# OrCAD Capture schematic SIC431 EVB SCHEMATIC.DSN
size Custom; title: SIC431 Demo Board; rev: D
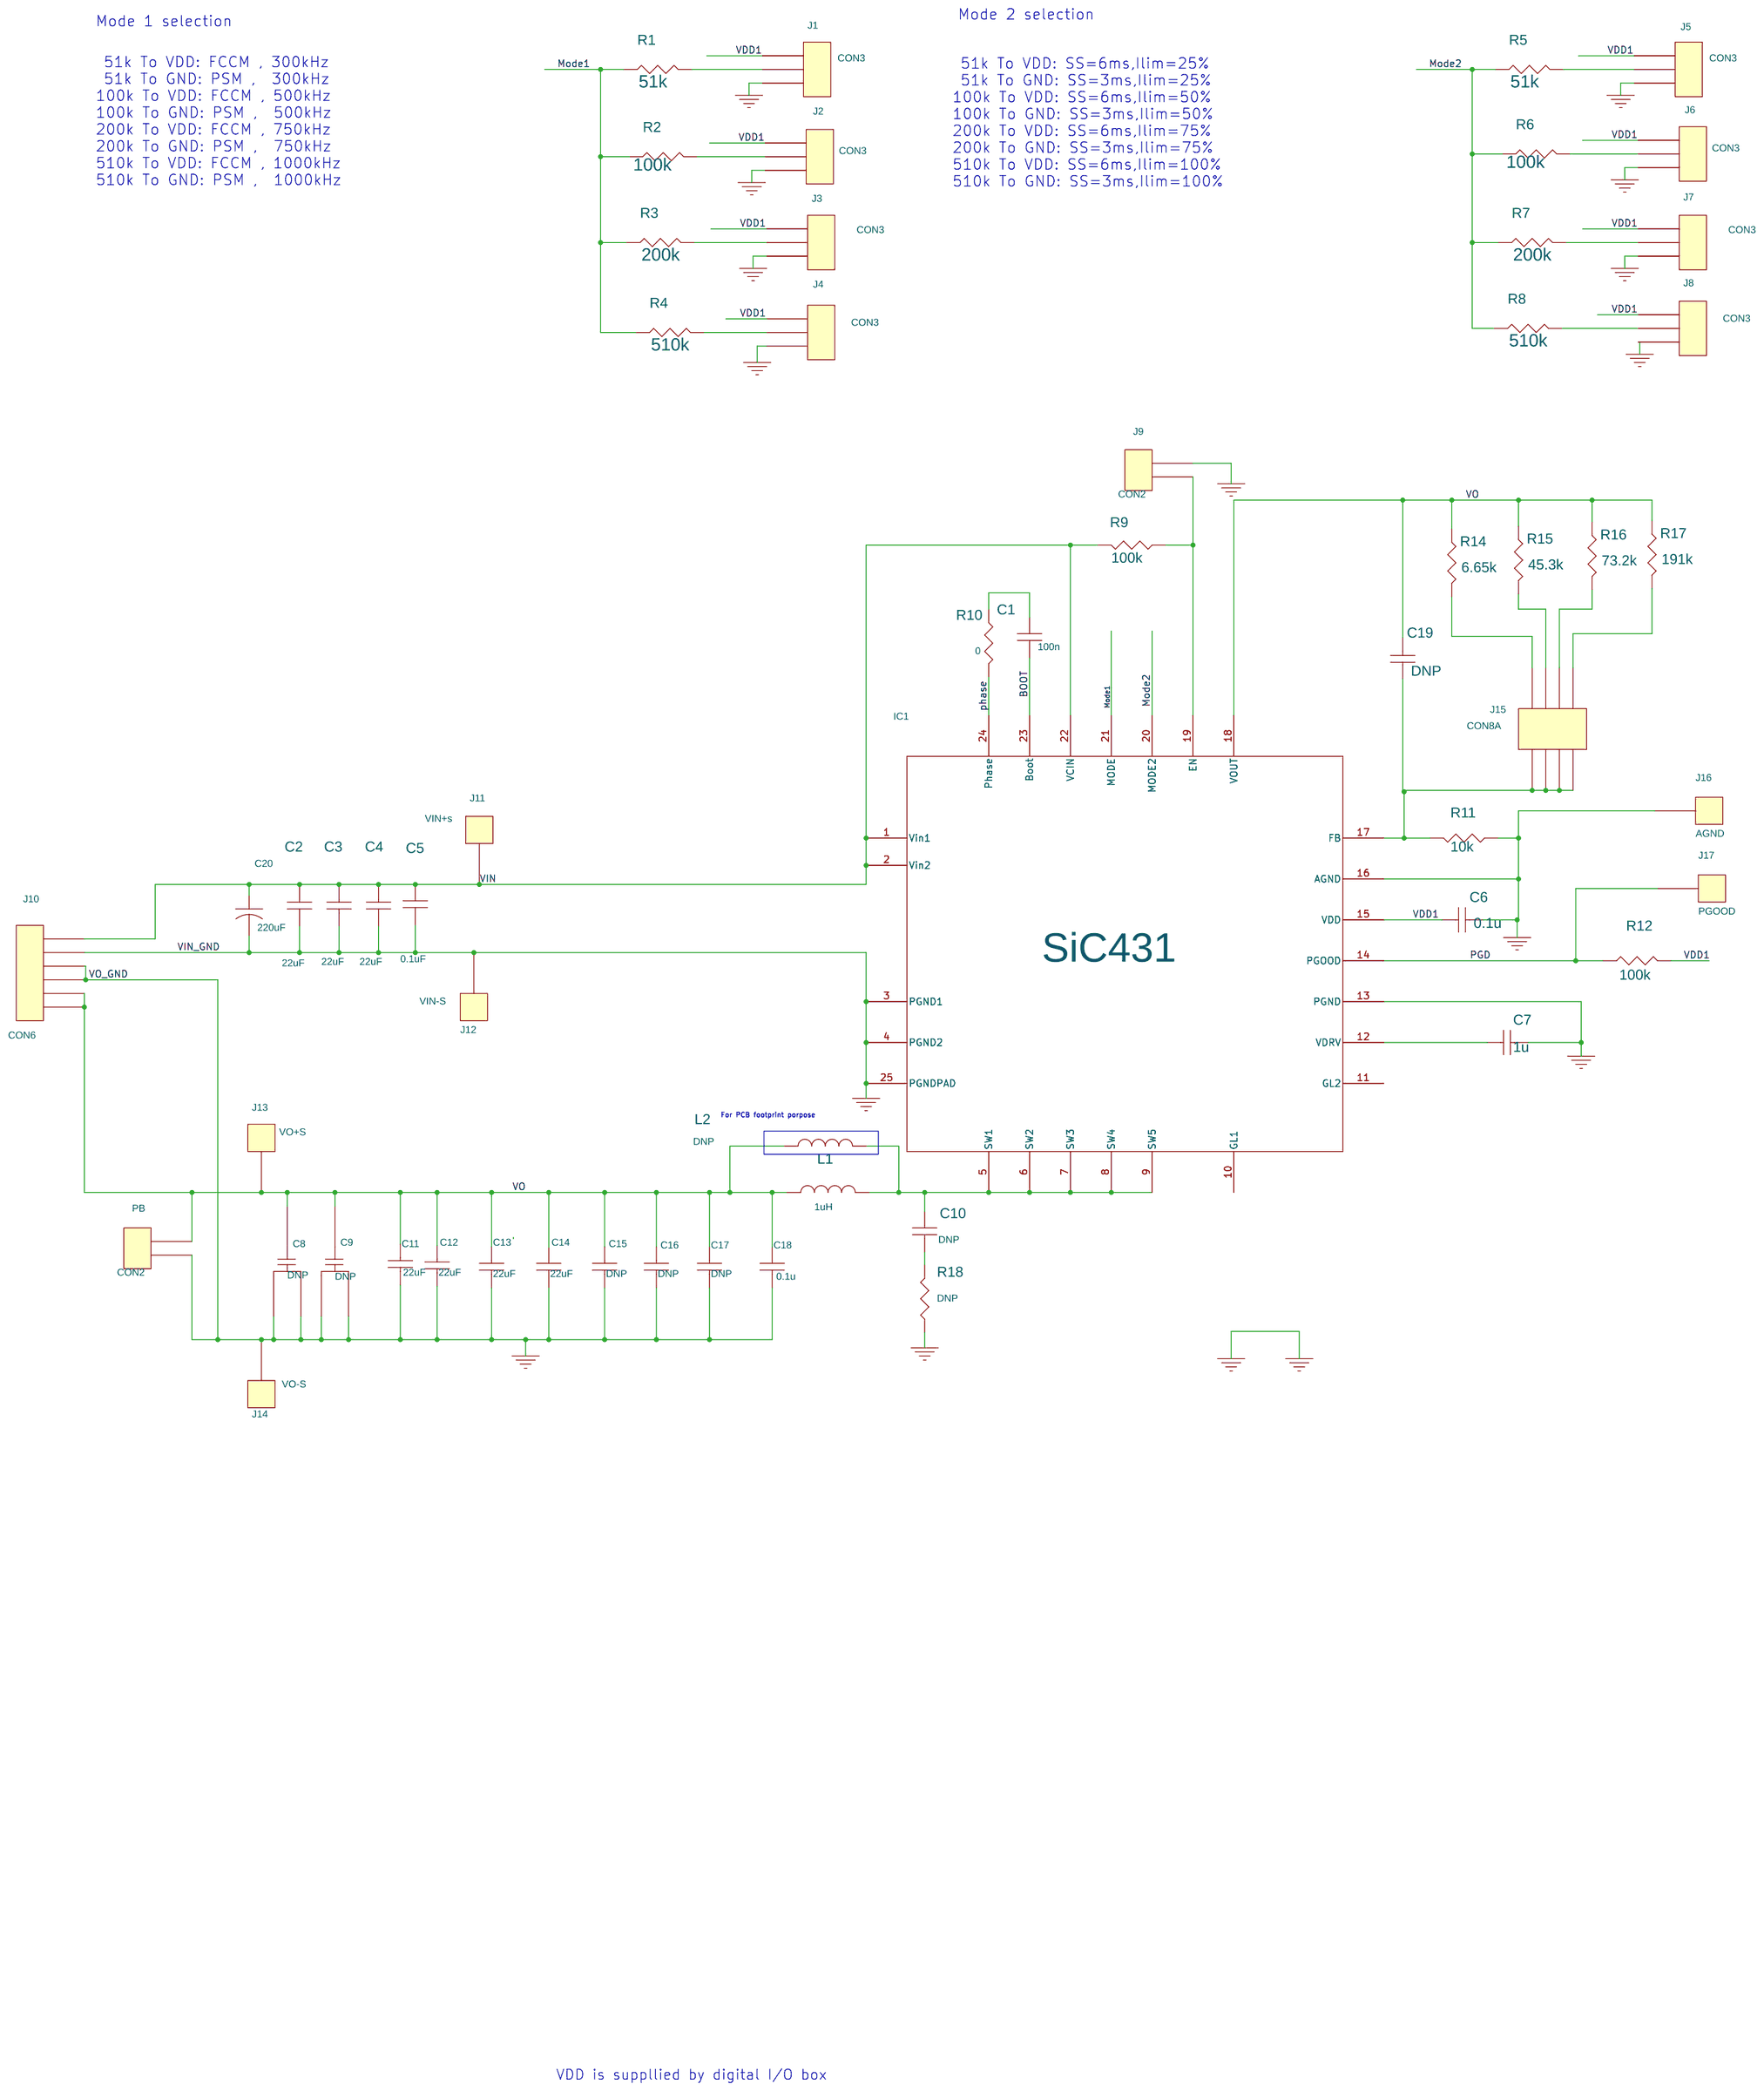
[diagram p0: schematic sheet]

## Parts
C1  100n  [C0402-TDK1]
C2  22uF  [C1210-TDK]
C3  22uF  [C1210-TDK]
C4  22uF  [C1210-TDK]
C5  0.1uF  [C0402-TDK]
C6  0.1u  [C0402-TDK1]
C7  1u  [C0603-TDK1]
C8  DNP  [poscap]
C9  DNP  [poscap]
C10  DNP  [C0603-TDK1]
C11  22uF  [C1210-TDK]
C12  22uF  [C1210-TDK]
C13  22uF  [C1210-TDK]
C14  22uF  [C1210-TDK]
C15  DNP  [C1210-TDK]
C16  DNP  [C1210-TDK]
C17  DNP  [C1210-TDK]
C18  0.1u  [C0603-TDK1]
C19  DNP  [C0603-TDK1]
C20  220uF  [CAP10p2x5]
IC1  SiC431  [sic431M]
J1  CON3  [minijumper3]
J2  CON3  [minijumper3]
J3  CON3  [minijumper3]
J4  CON3  [minijumper3]
J5  CON3  [minijumper3]
J6  CON3  [minijumper3]
J7  CON3  [minijumper3]
J8  CON3  [minijumper3]
J9  CON2  [minijumper2]
J10  CON6  [con6]
J11  VIN+s  [TP30]
J12  VIN-S  [TP30]
J13  VO+S  [TP30]
J14  VO-S  [TP30]
J15  CON8A  [minijumper2x4]
J16  AGND  [TP30]
J17  PGOOD  [TP30]
L1  1uH  [IHLP]
L2  DNP  [HCUVDE1]
PB  CON2  [2probe]
R1  51k  [R0402-vishay1]
R2  100k  [R0402-vishay1]
R3  200k  [R0402-vishay1]
R4  510k  [R0402-vishay1]
R5  51k  [R0402-vishay1]
R6  100k  [R0402-vishay1]
R7  200k  [R0402-vishay1]
R8  510k  [R0402-vishay1]
R9  100k  [R0402-vishay1]
R10  0  [R0402-vishay1]
R11  10k  [R0603-vishay]
R12  100k  [R0402-vishay1]
R14  6.65k  [R0603-vishay]
R15  45.3k  [R0603-vishay]
R16  73.2k  [R0603-vishay]
R17  191k  [R0603-vishay]
R18  DNP  [R1206-vishay]

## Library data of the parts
C1 C6 C11-C19 = CAPACITOR_NON-POL
C2-C4 = CAPACITOR_NON-POL: Part number: HMK325B7225KN-T
C5 = CAPACITOR_NON-POL: Part number: GCM188R72A103KA37D
C7 C10 = CAP_NP: Voltage: 50V
C8 C9 = POSCAP
C20 = CAP
IC1 = SiC431_2
J1-J8 = CON3: Part number: S9014E-03-ND
J9 PB = CON2
J10 = CON6: PN: 277-1581-ND
J11-J14 J16 J17 = CON1: MANUFACTURER: Keystone; Part Number: 1573-3
J15 = CON8A: part number: S9015E-04-ND
L1 L2 = INDUCTOR
R1-R8 R10 R12 R14-R17 = R
R9 R11 R18 = RESISTOR

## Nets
GND_POWER: C2.2 C3.2 C4.2 C5.2 C6.2 C7.2 C8.2(N1) C8.3(N2) C9.2(N1) C9.3(N2) C11.2 C12.2 C13.2 C14.2 C15.2 C16.2 C17.2 C18.2 C20.2 IC1.3(PGND1) IC1.4(PGND2) IC1.13(PGND) IC1.16(AGND) IC1.25(PGNDPAD) J1.3 J2.3 J3.3 J4.3 J5.3 J6.3 J7.3 J8.3 J9.1 J10.2 J10.3 J10.4 J12.1 J14.1 J16.1 PB.2 R11.1 R18.1
VDD1: C6.1 IC1.15(VDD) J1.1 J2.1 J3.1 J4.1 J5.1 J6.1 J7.1 J8.1 R12.2
VIN: C2.1 C3.1 C4.1 C5.1 C20.1 IC1.1(Vin1) IC1.2(Vin2) IC1.22(VCIN) J10.1 J11.1 R9.2
BOOT: C1.2 IC1.23(Boot)
Mode1: IC1.21(MODE) R1.1 R2.1 R3.1 R4.1
Mode2: IC1.20(MODE2) R5.1 R6.1 R7.1 R8.1
PGD: IC1.14(PGOOD) J17.1 R12.1
phase: IC1.24(Phase) R10.2
VO: C8.1(P) C9.1(P) C11.1 C12.1 C13.1 C14.1 C15.1 C16.1 C17.1 C18.1 C19.2 IC1.18(VOUT) J10.5 J10.6 J13.1 L1.1 L2.1 PB.1 R14.1 R15.1 R16.1 R17.1
N10425435: C10.1 IC1.5(SW1) IC1.6(SW2) IC1.7(SW3) IC1.8(SW4) IC1.9(SW5) L1.2 L2.2
N10425735: IC1.19(EN) J9.2 R9.1
N10425943: C1.1 R10.1
N10491860: C19.1 IC1.17(FB) J15.2 J15.4 J15.6 J15.8 R11.2
N10497600: C7.1 IC1.12(VDRV)
N10592056: J1.2 R1.2
N10592279: J2.2 R2.2
N10592308: J3.2 R3.2
N10592330: J4.2 R4.2
N10602058: J5.2 R5.2
N10602062: J6.2 R6.2
N10602066: J7.2 R7.2
N10602070: J8.2 R8.2
N10625993: C10.2 R18.2
N10654889: J15.1 R14.2
N10668036: J15.3 R15.2
N10668228: J15.5 R16.2
N10668284: J15.7 R17.2

Not connected (* = marked no-connect by the designer): IC1 10(GL1) 11(GL2)

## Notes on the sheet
- Mode 1 selection
- Mode 2 selection
- 51k To VDD: FCCM , 300kHz
   51k To GND: PSM ,  300kHz
  100k To VDD: FCCM , 500kHz
  100k To GND: PSM ,  500kHz
  200k To VDD: FCCM , 750kHz
  200k To GND: PSM ,  750kHz
  510k To VDD: FCCM , 1000kHz
  510k To GND: PSM ,  1000kHz
- 51k To VDD: SS=6ms,Ilim=25%
   51k To GND: SS=3ms,Ilim=25%
  100k To VDD: SS=6ms,Ilim=50%
  100k To GND: SS=3ms,Ilim=50%
  200k To VDD: SS=6ms,Ilim=75%
  200k To GND: SS=3ms,Ilim=75%
  510k To VDD: SS=6ms,Ilim=100%
  510k To GND: SS=3ms,Ilim=100%
- For PCB footprint porpose
- VDD is suppllied by digital I/O box
